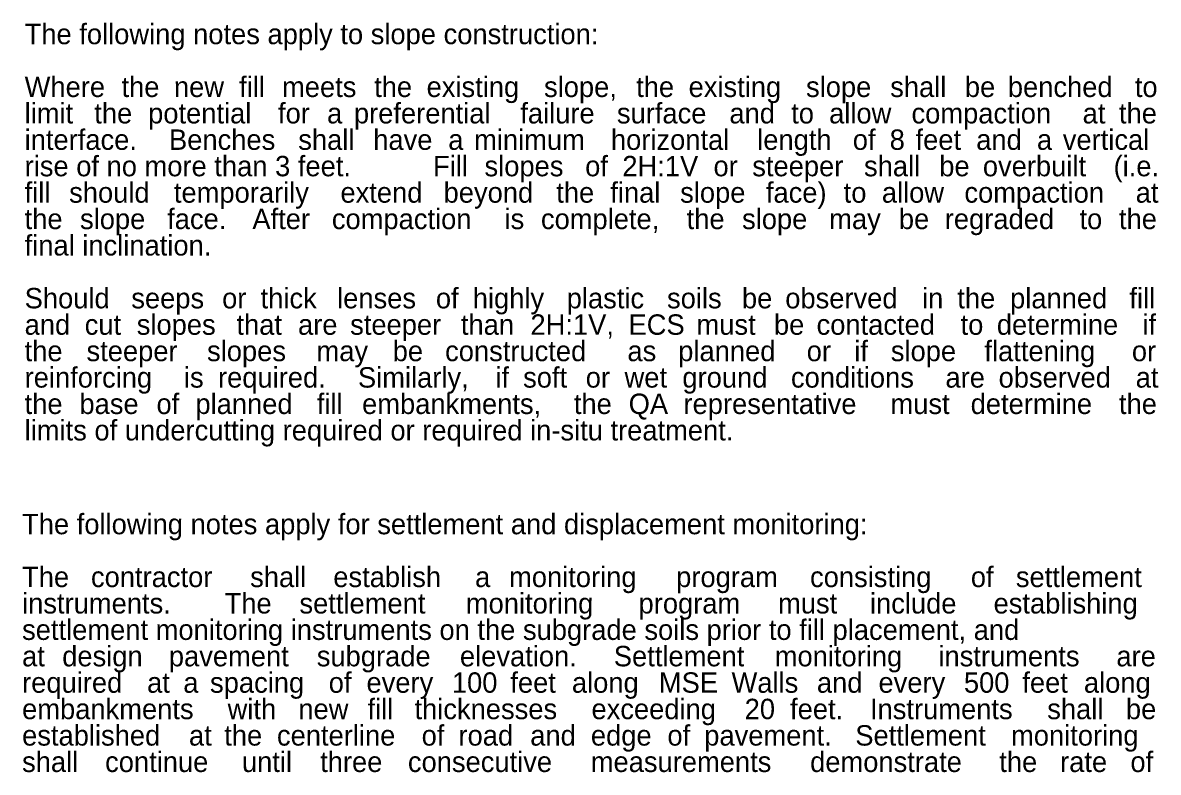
# Model space of a CAD drawing. Extents: x 4804 to 5434, y 4929 to 5221.
# Drawn here: x 5362.9 to 5432.9, y 5110.2 to 5156.4 of the extents above; entities that cross this region are included whole.
import ezdxf

# ---------------------------------------------------------------- set-up
doc = ezdxf.new("R2010")
doc.units = 0
doc.layers.add('RD_TX_RoadID', color=7, linetype='Continuous')

msp = doc.modelspace()

# ---------------------------------------------------------------- texts
at = {"layer": 'RD_TX_RoadID'}
for s, height, p in [('The following notes apply to slope construction:', 1.25864, (5362.975, 5155.076)), ('Where ', 1.2586, (5362.975, 5151.818)), ('the ', 1.2586, (5368.945, 5151.818)), ('fill ', 1.2586, (5376.194, 5151.818)), ('the ', 1.2586, (5384.517, 5151.818)), ('existing ', 1.2586, (5387.751, 5151.818)), ('slope, ', 1.2586, (5394.99, 5151.818)), ('the ', 1.2586, (5400.667, 5151.818)), ('existing ', 1.2586, (5403.9, 5151.818)), ('slope ', 1.2586, (5411.139, 5151.818)), ('shall ', 1.2586, (5416.327, 5151.818)), ('be ', 1.2586, (5420.93, 5151.818)), ('benched ', 1.2586, (5423.578, 5151.818)), ('new ', 1.2586, (5372.178, 5151.818)), ('meets ', 1.2586, (5378.84, 5151.818)), ('to ', 1.2586, (5431.404, 5151.818)), ('limit ', 1.2586, (5362.975, 5150.189)), ('the ', 1.2586, (5367.269, 5150.189)), ('potential ', 1.2586, (5370.586, 5150.189)), ('for ', 1.2586, (5378.592, 5150.189)), ('a ', 1.2586, (5381.615, 5150.189)), ('preferential ', 1.25864, (5383.273, 5150.189)), ('failure ', 1.2586, (5393.527, 5150.189)), ('surface ', 1.2586, (5399.482, 5150.189)), ('and ', 1.2586, (5406.416, 5150.189)), ('to ', 1.2586, (5410.223, 5150.189)), ('allow ', 1.2586, (5412.562, 5150.189)), ('compaction ', 1.25864, (5417.639, 5150.189)), ('at ', 1.2586, (5428.187, 5150.189)), ('the ', 1.2586, (5430.429, 5150.189)), ('interface. ', 1.25864, (5362.975, 5148.56)), (' Benches ', 1.2586, (5371.407, 5148.56)), ('shall ', 1.2586, (5379.841, 5148.56)), ('have ', 1.2586, (5384.463, 5148.56)), ('a ', 1.2586, (5389.086, 5148.56)), ('minimum ', 1.2586, (5390.679, 5148.56)), ('horizontal ', 1.25864, (5399.112, 5148.56)), ('length ', 1.2586, (5408.129, 5148.56)), ('of ', 1.2586, (5414.019, 5148.56)), ('8 ', 1.2586, (5416.294, 5148.56)), ('feet ', 1.2586, (5417.888, 5148.56)), ('and ', 1.2586, (5421.629, 5148.56)), ('a ', 1.2586, (5425.372, 5148.56)), ('vertical ', 1.2586, (5426.965, 5148.56)), ('rise of no more than 3 feet.', 1.25864, (5362.975, 5146.931)), ('Fill ', 1.2586, (5388.148, 5146.931)), ('slopes ', 1.2586, (5391.321, 5146.931)), ('of ', 1.2586, (5397.524, 5146.931)), ('2H:1V ', 1.2586, (5399.817, 5146.931)), ('shall ', 1.2586, (5414.712, 5146.931)), ('be ', 1.2586, (5419.352, 5146.931)), ('overbuilt ', 1.2586, (5422.037, 5146.931)), ('(i.e. ', 1.2586, (5430.095, 5146.931)), ('or ', 1.2586, (5405.434, 5146.931)), ('steeper ', 1.2586, (5407.825, 5146.931)), ('fill ', 1.2586, (5362.975, 5145.302)), ('should ', 1.2586, (5365.718, 5145.302)), ('temporarily ', 1.25864, (5372.173, 5145.302)), ('extend ', 1.2586, (5382.441, 5145.302)), ('beyond ', 1.2586, (5388.799, 5145.302)), ('the ', 1.2586, (5395.745, 5145.302)), ('final ', 1.2586, (5399.074, 5145.302)), ('slope ', 1.2586, (5403.38, 5145.302)), ('face) ', 1.2586, (5408.664, 5145.302)), ('to ', 1.2586, (5413.459, 5145.302)), ('allow ', 1.2586, (5415.811, 5145.302)), ('compaction ', 1.25864, (5420.9, 5145.302)), ('at ', 1.2586, (5431.46, 5145.302)), ('the ', 1.2586, (5362.975, 5143.673)), ('slope ', 1.2586, (5366.39, 5143.673)), ('face. ', 1.2586, (5371.759, 5143.673)), (' After ', 1.2586, (5376.543, 5143.673)), ('compaction ', 1.25864, (5381.91, 5143.673)), ('is ', 1.2586, (5392.555, 5143.673)), ('complete, ', 1.2586, (5394.798, 5143.673)), ('the ', 1.2586, (5403.782, 5143.673)), ('slope ', 1.2586, (5407.197, 5143.673)), ('may ', 1.2586, (5412.566, 5143.673)), ('be ', 1.2586, (5416.862, 5143.673)), ('regraded ', 1.2586, (5419.691, 5143.673)), ('to ', 1.2586, (5427.993, 5143.673)), ('the ', 1.2586, (5430.429, 5143.673)), ('final inclination.', 1.25864, (5362.975, 5142.044)), ('Should ', 1.2586, (5362.975, 5138.786)), ('seeps ', 1.2586, (5369.549, 5138.786)), ('or ', 1.2586, (5375.147, 5138.786)), ('thick ', 1.2586, (5377.52, 5138.786)), ('lenses ', 1.2586, (5382.236, 5138.786)), ('of ', 1.2586, (5388.323, 5138.786)), ('highly ', 1.2586, (5390.597, 5138.786)), ('plastic ', 1.2586, (5396.388, 5138.786)), ('soils ', 1.2586, (5402.571, 5138.786)), ('be ', 1.2586, (5407.191, 5138.786)), ('observed ', 1.2586, (5409.857, 5138.786)), ('in ', 1.2586, (5418.288, 5138.786)), ('the ', 1.2586, (5420.465, 5138.786)), ('planned ', 1.2586, (5423.716, 5138.786)), ('fill ', 1.2586, (5431.071, 5138.786)), ('and ', 1.2586, (5362.975, 5137.157)), ('cut ', 1.2586, (5366.676, 5137.157)), ('slopes ', 1.2586, (5369.886, 5137.157)), ('that ', 1.2586, (5376.03, 5137.157)), ('steeper ', 1.2586, (5383.039, 5137.157)), ('than ', 1.2586, (5389.866, 5137.157)), ('2H:1V, ', 1.2586, (5394.152, 5137.157)), ('ECS ', 1.2586, (5400.197, 5137.157)), ('must ', 1.2586, (5404.388, 5137.157)), ('be ', 1.2586, (5409.162, 5137.157)), ('contacted ', 1.2586, (5411.788, 5137.157)), ('to ', 1.2586, (5420.665, 5137.157)), ('determine ', 1.2586, (5422.899, 5137.157)), ('if ', 1.2586, (5431.875, 5137.157)), ('are ', 1.2586, (5379.826, 5137.157)), ('the ', 1.2586, (5362.975, 5135.529)), ('steeper ', 1.2586, (5366.789, 5135.529)), ('slopes ', 1.2586, (5374.22, 5135.529)), ('may ', 1.2586, (5380.966, 5135.529)), ('be ', 1.2586, (5385.662, 5135.529)), ('constructed ', 1.25864, (5388.891, 5135.529)), ('as ', 1.2586, (5400.13, 5135.529)), ('planned ', 1.2586, (5403.261, 5135.529)), ('or ', 1.2586, (5411.179, 5135.529)), ('if ', 1.2586, (5414.114, 5135.529)), ('slope ', 1.2586, (5416.365, 5135.529)), ('flattening ', 1.25864, (5422.134, 5135.529)), ('or ', 1.2586, (5431.221, 5135.529)), ('reinforcing ', 1.25864, (5362.975, 5133.9)), ('is ', 1.2586, (5372.793, 5133.9)), ('required. ', 1.2586, (5374.894, 5133.9)), (' Similarly, ', 1.25864, (5383.052, 5133.9)), ('if ', 1.2586, (5391.993, 5133.9)), ('soft ', 1.2586, (5393.701, 5133.9)), ('or ', 1.2586, (5397.559, 5133.9)), ('wet ', 1.2586, (5399.952, 5133.9)), ('ground ', 1.2586, (5403.518, 5133.9)), ('conditions ', 1.25864, (5410.209, 5133.9)), ('are ', 1.2586, (5419.733, 5133.9)), ('observed ', 1.2586, (5423.007, 5133.9)), ('at ', 1.2586, (5431.46, 5133.9)), ('the ', 1.2586, (5362.975, 5132.271)), ('base ', 1.2586, (5366.353, 5132.271)), ('of ', 1.2586, (5371.101, 5132.271)), ('planned ', 1.2586, (5373.502, 5132.271)), ('fill ', 1.2586, (5380.984, 5132.271)), ('embankments, ', 1.25864, (5383.775, 5132.271)), ('the ', 1.2586, (5396.828, 5132.271)), ('QA ', 1.2586, (5400.206, 5132.271)), ('representative ', 1.25864, (5403.585, 5132.271)), ('must ', 1.2586, (5416.344, 5132.271)), ('determine ', 1.2586, (5421.286, 5132.271)), ('the ', 1.2586, (5430.429, 5132.271)), ('limits of undercutting required or required in-situ treatment.', 1.25864, (5362.975, 5130.642)), ('The following notes apply for settlement and displacement monitoring:', 1.25864, (5362.818, 5124.857)), ('The ', 1.2586, (5362.818, 5121.599)), ('contractor ', 1.25864, (5367.063, 5121.599)), ('shall ', 1.2586, (5376.875, 5121.599)), ('establish ', 1.2586, (5382, 5121.599)), ('a ', 1.2586, (5390.739, 5121.599)), ('monitoring ', 1.25864, (5392.834, 5121.599)), ('program ', 1.2586, (5403.134, 5121.599)), ('consisting ', 1.25864, (5411.385, 5121.599)), ('of ', 1.2586, (5421.295, 5121.599)), ('settlement ', 1.25864, (5424.073, 5121.599)), ('instruments. ', 1.25864, (5362.818, 5119.97)), (' The ', 1.2586, (5374.833, 5119.97)), ('settlement ', 1.25864, (5379.913, 5119.97)), ('monitoring ', 1.25864, (5390.17, 5119.97)), ('program ', 1.2586, (5400.816, 5119.97)), ('must ', 1.2586, (5409.413, 5119.97)), ('include ', 1.2586, (5415.079, 5119.97)), ('establishing ', 1.25864, (5422.698, 5119.97)), ('settlement monitoring instruments on the subgrade soils prior to fill placement, and ', 1.25864, (5362.818, 5118.341)), ('at ', 1.2586, (5362.818, 5116.712)), ('design ', 1.2586, (5365.29, 5116.712)), ('pavement ', 1.2586, (5371.865, 5116.712)), ('subgrade ', 1.2586, (5380.982, 5116.712)), ('elevation. ', 1.25864, (5389.805, 5116.712)), (' Settlement ', 1.25864, (5398.823, 5116.712)), ('monitoring ', 1.25864, (5409.209, 5116.712)), ('instruments ', 1.25864, (5419.299, 5116.712)), ('are ', 1.2586, (5430.27, 5116.712)), ('required ', 1.2586, (5362.818, 5115.083)), ('at ', 1.2586, (5370.523, 5115.083)), ('a ', 1.2586, (5372.755, 5115.083)), ('spacing ', 1.2586, (5374.403, 5115.083)), ('of ', 1.2586, (5381.717, 5115.083)), ('every ', 1.2586, (5384.046, 5115.083)), ('100 ', 1.2586, (5389.31, 5115.083)), ('feet ', 1.2586, (5392.913, 5115.083)), ('along ', 1.2586, (5396.708, 5115.083)), ('MSE ', 1.2586, (5402.067, 5115.083)), ('Walls ', 1.2586, (5406.548, 5115.083)), ('and ', 1.2586, (5411.809, 5115.083)), ('every ', 1.2586, (5415.605, 5115.083)), ('500 ', 1.2586, (5420.869, 5115.083)), ('feet ', 1.2586, (5424.472, 5115.083)), ('along ', 1.2586, (5428.267, 5115.083)), ('embankments ', 1.25864, (5362.818, 5113.454)), ('with ', 1.2586, (5375.486, 5113.454)), ('fill ', 1.2586, (5384.11, 5113.454)), ('thicknesses ', 1.25864, (5387.004, 5113.454)), ('exceeding ', 1.2586, (5397.913, 5113.454)), ('20 ', 1.2586, (5407.356, 5113.454)), ('feet. ', 1.2586, (5410.155, 5113.454)), (' Instruments ', 1.25864, (5414.613, 5113.454)), ('shall ', 1.2586, (5426.007, 5113.454)), ('be ', 1.2586, (5430.857, 5113.454)), ('new ', 1.2586, (5379.846, 5113.454)), ('established ', 1.25864, (5362.818, 5111.825)), ('the ', 1.2586, (5375.278, 5111.825)), ('centerline ', 1.25864, (5378.528, 5111.825)), ('of ', 1.2586, (5387.445, 5111.825)), ('road ', 1.2586, (5389.717, 5111.825)), ('and ', 1.2586, (5394.139, 5111.825)), ('edge ', 1.2586, (5397.878, 5111.825)), ('of ', 1.2586, (5402.594, 5111.825)), ('Settlement ', 1.25864, (5414.175, 5111.825)), ('monitoring ', 1.25864, (5423.775, 5111.825)), ('at ', 1.2586, (5373.103, 5111.825)), ('pavement. ', 1.2586, (5404.866, 5111.825)), ('shall ', 1.2586, (5362.818, 5110.196)), ('continue ', 1.2586, (5367.934, 5110.196)), ('until ', 1.2586, (5376.37, 5110.196)), ('three ', 1.2586, (5381.19, 5110.196)), ('consecutive ', 1.25864, (5386.598, 5110.196)), ('measurements ', 1.25864, (5397.87, 5110.196)), ('demonstrate ', 1.25864, (5411.39, 5110.196)), ('the ', 1.2586, (5423.051, 5110.196)), ('rate ', 1.2586, (5426.798, 5110.196)), ('of ', 1.2586, (5431.132, 5110.196))]:
    msp.add_text(s, height=height, dxfattribs=at).set_placement(p)

doc.saveas('drawing.dxf')
